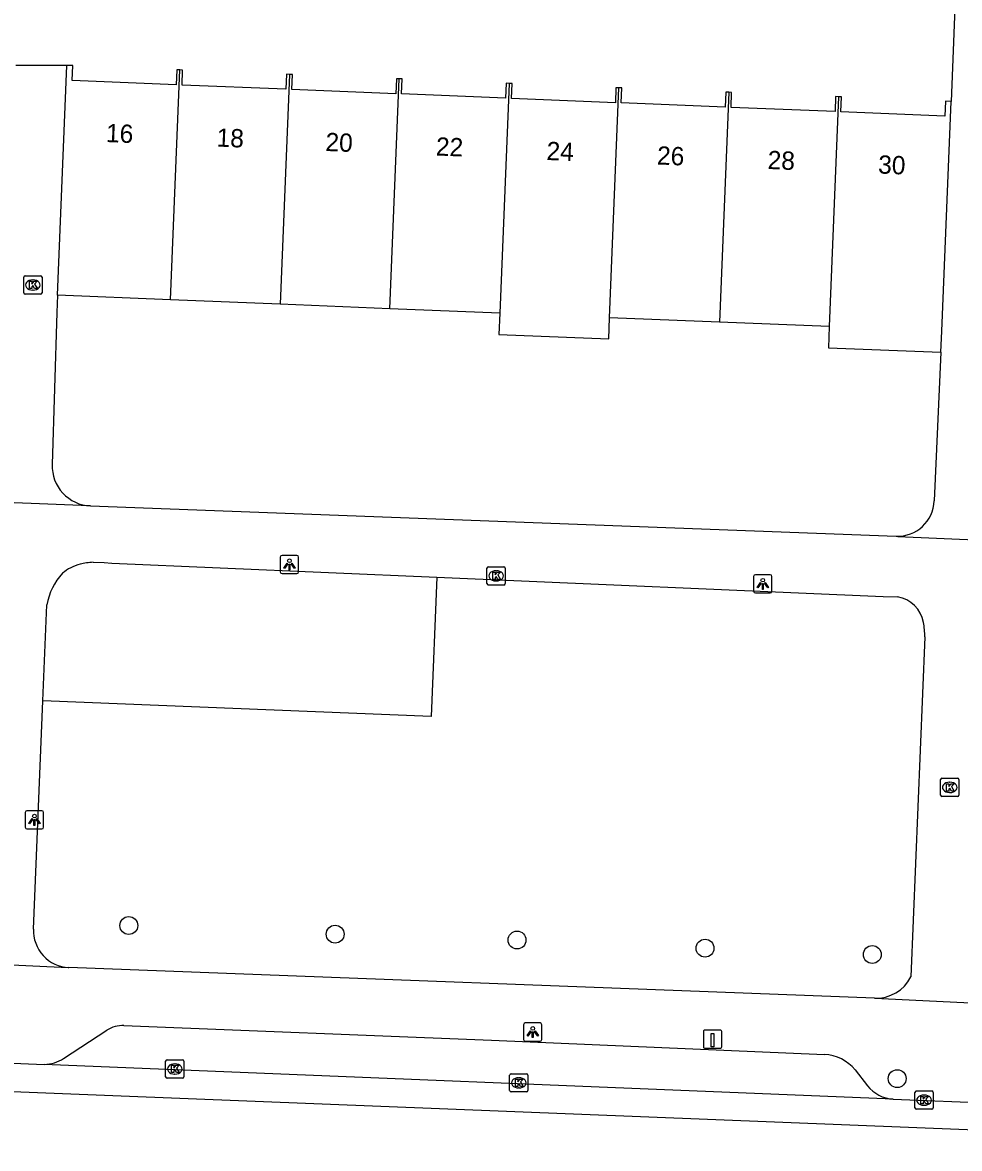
# Model space of a CAD drawing. Extents: x 160787 to 161428, y 386828 to 387483.
# Drawn here: x 161035.1 to 161086.3, y 386903.2 to 386964.7 of the extents above; entities that cross this region are included whole.
import ezdxf

# ---------------------------------------------------------------- set-up
doc = ezdxf.new("R2010")
doc.units = 0
for name, color, linetype in [('IMGEO_Boom', 7, 'Continuous'), ('IMGEO_Groenvoorziening', 7, 'Continuous'), ('IMGEO_Kolk', 7, 'Continuous'), ('IMGEO_Laadpaal', 7, 'Continuous'), ('IMGEO_Lichtpunt', 7, 'Continuous'), ('IMGEO_Pand', 7, 'Continuous'), ('IMGEO_Pand_nummerreeks', 7, 'Continuous'), ('IMGEO_Rijbaan_lokaal_gesloten', 7, 'Continuous'), ('IMGEO_Rijbaan_lokaal_open', 7, 'Continuous'), ('IMGEO_Voetpad_open', 7, 'Continuous')]:
    doc.layers.add(name, color=color, linetype=linetype)

msp = doc.modelspace()

# ---------------------------------------------------------------- linework, layer by layer
at = {"layer": 'IMGEO_Boom'}
for centre in [(161040.953, 386915.34), (161052.227, 386914.868), (161062.167, 386914.548), (161072.438, 386914.102), (161081.579, 386913.757), (161082.94, 386906.976)]:
    msp.add_circle(centre, 0.489, dxfattribs=at)
at = {"layer": 'IMGEO_Groenvoorziening'}
msp.add_lwpolyline([(161057.791, 386934.377), (161057.475, 386926.756), (161036.261, 386927.61)], dxfattribs=at)
at = {"layer": 'IMGEO_Kolk'}
for p, q in [((161035.212, 386949.912), (161035.212, 386950.764)), ((161035.287, 386950.838), (161036.139, 386950.838)), ((161035.7, 386950.618), (161035.725, 386950.618)), ((161036.213, 386950.764), (161036.213, 386949.912)), ((161035.723, 386950.058), (161035.698, 386950.058)), ((161036.139, 386949.838), (161035.287, 386949.838)), ((161060.523, 386934.02), (161060.523, 386934.872)), ((161060.598, 386934.946), (161061.45, 386934.946)), ((161061.011, 386934.726), (161061.036, 386934.726)), ((161061.524, 386934.872), (161061.524, 386934.02)), ((161061.45, 386933.946), (161060.598, 386933.946)), ((161061.034, 386934.166), (161061.009, 386934.166)), ((161085.309, 386922.463), (161085.309, 386923.315)), ((161085.384, 386923.389), (161086.236, 386923.389)), ((161085.797, 386923.169), (161085.822, 386923.169)), ((161086.31, 386923.315), (161086.31, 386922.463)), ((161086.236, 386922.389), (161085.384, 386922.389)), ((161085.82, 386922.609), (161085.795, 386922.609)), ((161042.967, 386907.078), (161042.967, 386907.93)), ((161043.042, 386908.004), (161043.894, 386908.004)), ((161043.455, 386907.784), (161043.48, 386907.784)), ((161043.968, 386907.93), (161043.968, 386907.078)), ((161043.894, 386907.004), (161043.042, 386907.004)), ((161043.478, 386907.224), (161043.453, 386907.224)), ((161061.764, 386906.321), (161061.764, 386907.173)), ((161061.839, 386907.247), (161062.691, 386907.247)), ((161062.252, 386907.027), (161062.277, 386907.027)), ((161062.765, 386907.173), (161062.765, 386906.321)), ((161062.275, 386906.467), (161062.25, 386906.467)), ((161083.982, 386906.301), (161084.834, 386906.301)), ((161062.691, 386906.247), (161061.839, 386906.247)), ((161083.907, 386905.375), (161083.907, 386906.227)), ((161084.395, 386906.081), (161084.42, 386906.081)), ((161084.908, 386906.227), (161084.908, 386905.375)), ((161084.834, 386905.301), (161083.982, 386905.301)), ((161084.418, 386905.521), (161084.393, 386905.521))]:
    msp.add_line(p, q, dxfattribs=at)
for points in [[(161035.212, 386949.912), (161035.212, 386950.764)], [(161035.287, 386950.838), (161036.139, 386950.838)], [(161036.213, 386950.764), (161036.213, 386949.912)], [(161035.533, 386950.538), (161035.656, 386950.538), (161035.656, 386950.387), (161035.786, 386950.538), (161035.95, 386950.538), (161035.804, 386950.387), (161035.957, 386950.138), (161035.805, 386950.138), (161035.72, 386950.302), (161035.656, 386950.235), (161035.656, 386950.138), (161035.533, 386950.138), (161035.533, 386950.538)], [(161036.139, 386949.838), (161035.287, 386949.838)], [(161060.523, 386934.02), (161060.523, 386934.872)], [(161060.598, 386934.946), (161061.45, 386934.946)], [(161060.844, 386934.646), (161060.967, 386934.646), (161060.967, 386934.495), (161061.097, 386934.646), (161061.261, 386934.646), (161061.115, 386934.495), (161061.268, 386934.246), (161061.116, 386934.246), (161061.031, 386934.41), (161060.967, 386934.343), (161060.967, 386934.246), (161060.844, 386934.246), (161060.844, 386934.646)], [(161061.524, 386934.872), (161061.524, 386934.02)], [(161061.45, 386933.946), (161060.598, 386933.946)], [(161085.309, 386922.463), (161085.309, 386923.315)], [(161085.384, 386923.389), (161086.236, 386923.389)], [(161085.63, 386923.089), (161085.753, 386923.089), (161085.753, 386922.938), (161085.883, 386923.089), (161086.047, 386923.089), (161085.901, 386922.938), (161086.054, 386922.689), (161085.902, 386922.689), (161085.817, 386922.853), (161085.753, 386922.786), (161085.753, 386922.689), (161085.63, 386922.689), (161085.63, 386923.089)], [(161086.31, 386923.315), (161086.31, 386922.463)], [(161086.236, 386922.389), (161085.384, 386922.389)], [(161042.967, 386907.078), (161042.967, 386907.93)], [(161043.042, 386908.004), (161043.894, 386908.004)], [(161043.288, 386907.704), (161043.411, 386907.704), (161043.411, 386907.553), (161043.541, 386907.704), (161043.705, 386907.704), (161043.559, 386907.553), (161043.712, 386907.304), (161043.56, 386907.304), (161043.475, 386907.468), (161043.411, 386907.401), (161043.411, 386907.304), (161043.288, 386907.304), (161043.288, 386907.704)], [(161043.968, 386907.93), (161043.968, 386907.078)], [(161043.894, 386907.004), (161043.042, 386907.004)], [(161061.764, 386906.321), (161061.764, 386907.173)], [(161061.839, 386907.247), (161062.691, 386907.247)], [(161062.085, 386906.947), (161062.208, 386906.947), (161062.208, 386906.796), (161062.338, 386906.947), (161062.502, 386906.947), (161062.356, 386906.796), (161062.509, 386906.547), (161062.357, 386906.547), (161062.272, 386906.711), (161062.208, 386906.644), (161062.208, 386906.547), (161062.085, 386906.547), (161062.085, 386906.947)], [(161062.765, 386907.173), (161062.765, 386906.321)], [(161083.982, 386906.301), (161084.834, 386906.301)], [(161062.691, 386906.247), (161061.839, 386906.247)], [(161083.907, 386905.375), (161083.907, 386906.227)], [(161084.228, 386906.001), (161084.351, 386906.001), (161084.351, 386905.85), (161084.481, 386906.001), (161084.645, 386906.001), (161084.499, 386905.85), (161084.652, 386905.601), (161084.5, 386905.601), (161084.415, 386905.765), (161084.351, 386905.698), (161084.351, 386905.601), (161084.228, 386905.601), (161084.228, 386906.001)], [(161084.908, 386906.227), (161084.908, 386905.375)], [(161084.834, 386905.301), (161083.982, 386905.301)]]:
    msp.add_lwpolyline(points, dxfattribs=at)
for centre, start, end in [((161035.289, 386950.762), 91.55205, 178.44795), ((161035.289, 386950.762), 91.55205, 178.44795), ((161036.137, 386950.762), 1.55205, 88.44795), ((161036.137, 386950.762), 1.55205, 88.44795), ((161035.289, 386949.914), 181.55205, 268.44795), ((161035.289, 386949.914), 181.55205, 268.44795), ((161036.137, 386949.914), 271.55205, 358.44795), ((161036.137, 386949.914), 271.55205, 358.44795), ((161060.6, 386934.87), 91.55205, 178.44795), ((161060.6, 386934.87), 91.55205, 178.44795), ((161061.448, 386934.87), 1.55205, 88.44795), ((161061.448, 386934.87), 1.55205, 88.44795), ((161060.6, 386934.022), 181.55205, 268.44795), ((161060.6, 386934.022), 181.55205, 268.44795), ((161061.448, 386934.022), 271.55205, 358.44795), ((161061.448, 386934.022), 271.55205, 358.44795), ((161085.386, 386923.313), 91.55205, 178.44795), ((161085.386, 386923.313), 91.55205, 178.44795), ((161086.234, 386923.313), 1.55205, 88.44795), ((161086.234, 386923.313), 1.55205, 88.44795), ((161085.386, 386922.465), 181.55205, 268.44795), ((161085.386, 386922.465), 181.55205, 268.44795), ((161086.234, 386922.465), 271.55205, 358.44795), ((161086.234, 386922.465), 271.55205, 358.44795), ((161043.044, 386907.928), 91.55205, 178.44795), ((161043.044, 386907.928), 91.55205, 178.44795), ((161043.892, 386907.928), 1.55205, 88.44795), ((161043.892, 386907.928), 1.55205, 88.44795), ((161043.044, 386907.08), 181.55205, 268.44795), ((161043.044, 386907.08), 181.55205, 268.44795), ((161043.892, 386907.08), 271.55205, 358.44795), ((161043.892, 386907.08), 271.55205, 358.44795), ((161061.841, 386907.171), 91.55205, 178.44795), ((161061.841, 386907.171), 91.55205, 178.44795), ((161062.689, 386907.171), 1.55205, 88.44795), ((161062.689, 386907.171), 1.55205, 88.44795), ((161061.841, 386906.323), 181.55205, 268.44795), ((161061.841, 386906.323), 181.55205, 268.44795), ((161062.689, 386906.323), 271.55205, 358.44795), ((161062.689, 386906.323), 271.55205, 358.44795), ((161083.984, 386906.225), 91.55205, 178.44795), ((161083.984, 386906.225), 91.55205, 178.44795), ((161084.832, 386906.225), 1.55205, 88.44795), ((161084.832, 386906.225), 1.55205, 88.44795), ((161083.984, 386905.377), 181.55205, 268.44795), ((161083.984, 386905.377), 181.55205, 268.44795), ((161084.832, 386905.377), 271.55205, 358.44795), ((161084.832, 386905.377), 271.55205, 358.44795)]:
    msp.add_arc(centre, 0.0765, start, end, dxfattribs=at)
for centre, major_axis, ratio, start_param, end_param in [((161035.699, 386950.338), (-0.387, 0.002), 0.722429, 4.712389, 7.853982), ((161035.724, 386950.338), (-0.39, 0.002), 0.717154, 1.570796, 4.712389), ((161061.01, 386934.446), (-0.387, 0.002), 0.722429, 4.712389, 7.853982), ((161061.035, 386934.446), (-0.39, 0.002), 0.717154, 1.570796, 4.712389), ((161085.796, 386922.889), (-0.387, 0.002), 0.722429, 4.712389, 7.853982), ((161085.821, 386922.889), (-0.39, 0.002), 0.717154, 1.570796, 4.712389), ((161043.454, 386907.504), (-0.387, 0.002), 0.722429, 4.712389, 7.853982), ((161043.479, 386907.504), (-0.39, 0.002), 0.717154, 1.570796, 4.712389), ((161062.251, 386906.747), (-0.387, 0.002), 0.722429, 4.712389, 7.853982), ((161062.276, 386906.747), (-0.39, 0.002), 0.717154, 1.570796, 4.712389), ((161084.394, 386905.801), (-0.387, 0.002), 0.722429, 4.712389, 7.853982), ((161084.419, 386905.801), (-0.39, 0.002), 0.717154, 1.570796, 4.712389)]:
    msp.add_ellipse(centre, major_axis=major_axis, ratio=ratio, start_param=start_param, end_param=end_param, dxfattribs=at)
at = {"layer": 'IMGEO_Laadpaal'}
for p, q in [((161072.351, 386909.549), (161072.351, 386908.708)), ((161072.351, 386909.549), (161072.351, 386908.708)), ((161073.267, 386909.633), (161072.426, 386909.633)), ((161073.267, 386909.633), (161072.426, 386909.633)), ((161073.351, 386908.717), (161073.351, 386909.558)), ((161073.351, 386908.717), (161073.351, 386909.558)), ((161072.435, 386908.633), (161073.276, 386908.633)), ((161072.435, 386908.633), (161073.276, 386908.633))]:
    msp.add_line(p, q, dxfattribs=at)
msp.add_lwpolyline([(161072.766, 386909.446), (161072.926, 386909.446), (161072.926, 386908.713), (161072.766, 386908.713), (161072.766, 386909.446)], dxfattribs=at)
for centre, start, end in [((161072.429, 386909.555), 92.4484, 184.28452), ((161072.429, 386909.555), 92.4484, 184.28452), ((161073.273, 386909.555), 2.4484, 94.28452), ((161073.273, 386909.555), 2.4484, 94.28452), ((161073.273, 386908.711), 272.4484, 4.28452), ((161073.273, 386908.711), 272.4484, 4.28452), ((161072.429, 386908.711), 182.4484, 274.28452), ((161072.429, 386908.711), 182.4484, 274.28452)]:
    msp.add_arc(centre, 0.0779, start, end, dxfattribs=at)
at = {"layer": 'IMGEO_Lichtpunt'}
for p, q in [((161049.232, 386935.472), (161049.232, 386934.665)), ((161049.232, 386935.472), (161049.232, 386934.665)), ((161050.134, 386935.567), (161049.326, 386935.567)), ((161050.134, 386935.567), (161049.326, 386935.567)), ((161050.228, 386934.665), (161050.228, 386935.472)), ((161050.228, 386934.665), (161050.228, 386935.472)), ((161049.326, 386934.571), (161050.134, 386934.571)), ((161049.326, 386934.571), (161050.134, 386934.571)), ((161075.094, 386934.413), (161075.094, 386933.606)), ((161075.094, 386934.413), (161075.094, 386933.606)), ((161075.996, 386934.508), (161075.188, 386934.508)), ((161075.996, 386934.508), (161075.188, 386934.508)), ((161076.09, 386933.606), (161076.09, 386934.413)), ((161076.09, 386933.606), (161076.09, 386934.413)), ((161075.188, 386933.512), (161075.996, 386933.512)), ((161075.188, 386933.512), (161075.996, 386933.512)), ((161035.298, 386921.521), (161035.298, 386920.714)), ((161035.298, 386921.521), (161035.298, 386920.714)), ((161036.2, 386921.616), (161035.392, 386921.616)), ((161036.2, 386921.616), (161035.392, 386921.616)), ((161036.294, 386920.714), (161036.294, 386921.521)), ((161036.294, 386920.714), (161036.294, 386921.521)), ((161035.392, 386920.62), (161036.2, 386920.62)), ((161035.392, 386920.62), (161036.2, 386920.62)), ((161063.427, 386910.018), (161062.619, 386910.018)), ((161063.427, 386910.018), (161062.619, 386910.018)), ((161062.525, 386909.923), (161062.525, 386909.116)), ((161062.525, 386909.923), (161062.525, 386909.116)), ((161063.521, 386909.116), (161063.521, 386909.923)), ((161063.521, 386909.116), (161063.521, 386909.923)), ((161062.619, 386909.022), (161063.427, 386909.022)), ((161062.619, 386909.022), (161063.427, 386909.022))]:
    msp.add_line(p, q, dxfattribs=at)
for points in [[(161049.606, 386935.136), (161049.645, 386935.108), (161049.457, 386934.846), (161049.419, 386934.873), (161049.606, 386935.136)], [(161049.708, 386935.088), (161049.755, 386935.088), (161049.755, 386934.766), (161049.708, 386934.766), (161049.708, 386935.088)], [(161049.818, 386935.108), (161049.856, 386935.135), (161050.043, 386934.873), (161050.004, 386934.845), (161049.818, 386935.108)], [(161075.468, 386934.077), (161075.507, 386934.049), (161075.319, 386933.787), (161075.281, 386933.814), (161075.468, 386934.077)], [(161075.57, 386934.029), (161075.617, 386934.029), (161075.617, 386933.707), (161075.57, 386933.707), (161075.57, 386934.029)], [(161075.68, 386934.049), (161075.718, 386934.076), (161075.905, 386933.814), (161075.866, 386933.786), (161075.68, 386934.049)], [(161035.672, 386921.185), (161035.711, 386921.157), (161035.523, 386920.895), (161035.485, 386920.922), (161035.672, 386921.185)], [(161035.774, 386921.137), (161035.821, 386921.137), (161035.821, 386920.815), (161035.774, 386920.815), (161035.774, 386921.137)], [(161035.884, 386921.157), (161035.922, 386921.184), (161036.109, 386920.922), (161036.07, 386920.894), (161035.884, 386921.157)], [(161062.899, 386909.587), (161062.938, 386909.559), (161062.75, 386909.297), (161062.712, 386909.324), (161062.899, 386909.587)], [(161063.001, 386909.539), (161063.048, 386909.539), (161063.048, 386909.217), (161063.001, 386909.217), (161063.001, 386909.539)], [(161063.111, 386909.559), (161063.149, 386909.586), (161063.336, 386909.324), (161063.297, 386909.296), (161063.111, 386909.559)]]:
    msp.add_lwpolyline(points, dxfattribs=at)
for centre in [(161049.731, 386935.27), (161075.593, 386934.211), (161035.797, 386921.319), (161063.024, 386909.721)]:
    msp.add_circle(centre, 0.0994, dxfattribs=at)
for centre, start, end in [((161049.326, 386935.472), 90, 180), ((161049.326, 386935.472), 90, 180), ((161050.134, 386935.472), 0, 90), ((161050.134, 386935.472), 0, 90), ((161049.326, 386934.665), 180, 270), ((161049.326, 386934.665), 180, 270), ((161050.134, 386934.665), 270, 0), ((161050.134, 386934.665), 270, 360), ((161075.188, 386934.413), 90, 180), ((161075.188, 386934.413), 90, 180), ((161075.996, 386934.413), 0, 90), ((161075.996, 386934.413), 0, 90), ((161075.188, 386933.606), 180, 270), ((161075.188, 386933.606), 180, 270), ((161075.996, 386933.606), 270, 0), ((161075.996, 386933.606), 270, 360), ((161035.392, 386921.521), 90, 180), ((161035.392, 386921.521), 90, 180), ((161036.2, 386921.521), 0, 90), ((161036.2, 386921.521), 0, 90), ((161035.392, 386920.714), 180, 270), ((161035.392, 386920.714), 180, 270), ((161036.2, 386920.714), 270, 0), ((161036.2, 386920.714), 270, 360), ((161062.619, 386909.923), 90, 180), ((161062.619, 386909.923), 90, 180), ((161063.427, 386909.923), 0, 90), ((161063.427, 386909.923), 0, 90), ((161062.619, 386909.116), 180, 270), ((161062.619, 386909.116), 180, 270), ((161063.427, 386909.116), 270, 0), ((161063.427, 386909.116), 270, 360)]:
    msp.add_arc(centre, 0.0946, start, end, dxfattribs=at)
at = {"layer": 'IMGEO_Pand'}
for points in [[(161037.064, 386949.777), (161037.575, 386962.338)], [(161043.735, 386962.088), (161043.575, 386962.094), (161043.542, 386961.275), (161037.862, 386961.506), (161037.895, 386962.325), (161037.575, 386962.338)], [(161043.224, 386949.526), (161043.735, 386962.088)], [(161049.735, 386961.843), (161049.575, 386961.85), (161049.542, 386961.031), (161043.862, 386961.262), (161043.895, 386962.081), (161043.735, 386962.088)], [(161049.735, 386961.843), (161049.224, 386949.282)], [(161055.735, 386961.6), (161055.575, 386961.606), (161055.542, 386960.787), (161049.862, 386961.018), (161049.895, 386961.837), (161049.735, 386961.843)], [(161055.224, 386949.038), (161055.735, 386961.6)], [(161061.735, 386961.355), (161061.575, 386961.362), (161061.542, 386960.543), (161055.862, 386960.774), (161055.895, 386961.593), (161055.735, 386961.6)], [(161061.735, 386961.355), (161061.224, 386948.793)], [(161067.735, 386961.11), (161067.574, 386961.117), (161067.541, 386960.298), (161061.861, 386960.529), (161061.894, 386961.348), (161061.735, 386961.355)], [(161067.224, 386948.549), (161067.735, 386961.11)], [(161073.735, 386960.866), (161073.574, 386960.873), (161073.541, 386960.054), (161067.861, 386960.285), (161067.894, 386961.104), (161067.735, 386961.11)], [(161073.735, 386960.866), (161073.224, 386948.305)], [(161079.735, 386960.622), (161079.574, 386960.629), (161079.541, 386959.81), (161073.861, 386960.041), (161073.894, 386960.86), (161073.735, 386960.866)], [(161079.735, 386960.622), (161079.224, 386948.061)], [(161085.893, 386960.371), (161085.574, 386960.385), (161085.541, 386959.566), (161079.861, 386959.797), (161079.894, 386960.616), (161079.735, 386960.622)], [(161085.314, 386946.66), (161085.382, 386947.81), (161085.893, 386960.371)], [(161043.224, 386949.526), (161037.064, 386949.777)], [(161049.224, 386949.282), (161043.224, 386949.526)], [(161055.224, 386949.038), (161049.224, 386949.282)], [(161061.224, 386948.793), (161055.224, 386949.038)], [(161061.224, 386948.793), (161061.177, 386947.641), (161067.187, 386947.397), (161067.224, 386948.549)], [(161073.224, 386948.305), (161067.224, 386948.549)], [(161079.224, 386948.061), (161073.224, 386948.305)], [(161079.224, 386948.061), (161079.177, 386946.91), (161085.314, 386946.66)]]:
    msp.add_lwpolyline(points, dxfattribs=at)
at = {"layer": 'IMGEO_Rijbaan_lokaal_gesloten'}
for points in [[(161112.394, 386903.16), (160997.039, 386907.744)], [(161031.606, 386907.949), (161036.335, 386907.755)], [(161082.721, 386905.854), (161036.335, 386907.755)], [(161082.721, 386905.854), (161088.199, 386905.631)]]:
    msp.add_lwpolyline(points, dxfattribs=at)
at = {"layer": 'IMGEO_Rijbaan_lokaal_open'}
for points in [[(161086.985, 386988.287), (161085.893, 386960.371)], [(161037.575, 386962.338), (161034.774, 386962.328)]]:
    msp.add_lwpolyline(points, dxfattribs=at)
at = {"layer": 'IMGEO_Voetpad_open'}
for points in [[(161037.064, 386949.777), (161037.025, 386948.827), (161036.769, 386940.526)], [(161085.314, 386946.66), (161084.964, 386938.541)], [(161038.862, 386938.273), (161038.808, 386938.265), (161031.942, 386938.539), (161031.883, 386938.55)], [(161038.862, 386938.273), (161082.88, 386936.613)], [(161082.88, 386936.613), (161082.967, 386936.595), (161090.15, 386936.295), (161090.255, 386936.31)], [(161039.007, 386935.188), (161039.604, 386935.179), (161040.028, 386935.144), (161057.791, 386934.377)], [(161057.791, 386934.377), (161082.168, 386933.326), (161082.96, 386933.292)], [(161036.261, 386927.61), (161036.479, 386932.865)], [(161084.442, 386931.117), (161083.689, 386912.534)], [(161035.745, 386915.15), (161036.261, 386927.61)], [(161031.046, 386913.363), (161031.075, 386913.358), (161037.636, 386913.046), (161037.68, 386913.05)], [(161081.696, 386911.369), (161037.68, 386913.05)], [(161081.696, 386911.369), (161081.725, 386911.364), (161088.828, 386911.021), (161088.857, 386911.024)], [(161037.392, 386908.079), (161039.753, 386909.621)], [(161040.691, 386909.878), (161060.77, 386909.075), (161078.966, 386908.298)], [(161080.633, 386907.449), (161081.315, 386906.589)]]:
    msp.add_lwpolyline(points, dxfattribs=at)
for centre, radius, start, end in [((161038.939, 386940.443), 2.171, 177.8058, 267.97736), ((161082.956, 386938.621), 2.009, 267.81828, 357.72826), ((161039.199, 386931.569), 3.624, 93.03769, 104.47876), ((161039.757, 386932.317), 3.323, 136.95442, 170.50326), ((161038.858, 386932.781), 2.365, 103.81826, 130.30498), ((161082.715, 386931.633), 1.676, 9.25161, 81.60811), ((161081.297, 386931.225), 3.147, 358.03055, 12.43717), ((161037.761, 386915.066), 2.018, 177.61782, 267.69889), ((161081.774, 386913.522), 2.155, 267.91485, 332.70164), ((161040.627, 386908.27), 1.61, 87.73908, 122.90549), ((161078.867, 386906.042), 2.258, 38.54177, 87.47891), ((161036.312, 386909.715), 1.96, 270.66319, 303.42034), ((161082.843, 386907.8), 1.95, 218.39967, 266.40283)]:
    msp.add_arc(centre, radius, start, end, dxfattribs=at)

# ---------------------------------------------------------------- texts
at = {"layer": 'IMGEO_Pand_nummerreeks'}
for s, rotation, p in [('16', 357.67001, (161039.694, 386958.149)), ('18', 357.67001, (161045.736, 386957.903)), ('20', 357.67001, (161051.685, 386957.661)), ('22', 357.67001, (161057.719, 386957.415)), ('24', 357.66806, (161063.762, 386957.169)), ('26', 357.67001, (161069.801, 386956.924)), ('28', 357.67001, (161075.844, 386956.678)), ('30', 357.66806, (161081.884, 386956.431))]:
    msp.add_text(s, height=1, rotation=rotation, dxfattribs=at).set_placement(p)

doc.saveas('drawing.dxf')
